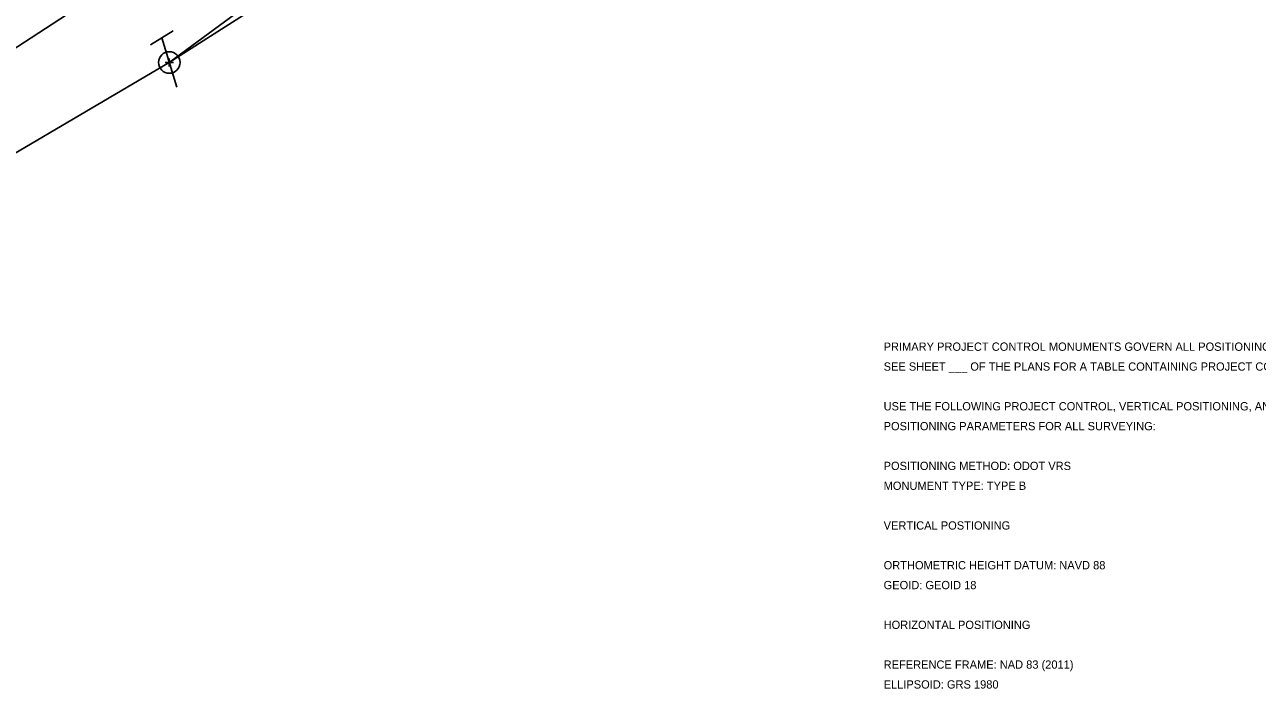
# Model space of a CAD drawing. Extents: x 2048206 to 2051708, y 354200 to 357644.
# Drawn here: x 2049380.8 to 2049529.9, y 356157.9 to 356238.7 of the extents above; entities that cross this region are included whole.
import ezdxf

# ---------------------------------------------------------------- set-up
doc = ezdxf.new("R2010")
doc.units = 0
for name, color, linetype in [('RW_X_CL_1000_Cardinal_Points', 7, 'Continuous'), ('RW_X_CL_500_Bearings', 7, 'Continuous'), ('SC_Scratch1', 7, 'Continuous'), ('SV_X_Text', 7, 'Continuous'), ('UT_X_Cable_TV', 7, 'Continuous')]:
    doc.layers.add(name, color=color, linetype=linetype)

msp = doc.modelspace()

# ---------------------------------------------------------------- linework, layer by layer
at = {"layer": 'RW_X_CL_1000_Cardinal_Points'}
for p in [(2049173.02, 356101.71), (2049173.02, 356101.71), (2049398.29, 356234.18), (2049398.29, 356234.18)]:
    msp.add_line(p, (2049557.32, 356351.32), dxfattribs=at)
at = {"layer": 'RW_X_CL_500_Bearings'}
for p, q in [((2049398.75, 356237.99), (2049396.03, 356236.31)), ((2049397.39, 356237.15), (2049399.18, 356231.2))]:
    msp.add_line(p, q, dxfattribs=at)
msp.add_circle((2049398.29, 356234.18), 1.3, dxfattribs=at)
at = {"layer": 'SC_Scratch1'}
for p, q in [((2049397.79, 356234.18), (2049398.79, 356234.18)), ((2049398.29, 356234.68), (2049398.29, 356233.68)), ((2049398.29, 356234.18), (2049398.29, 356234.18))]:
    msp.add_line(p, q, dxfattribs=at)
at = {"layer": 'UT_X_Cable_TV'}
msp.add_lwpolyline([(2049173.02, 356101.71), (2049398.29, 356234.18), (2049648.28, 356393.26), (2049839.38, 356550.87), (2049967.48, 356704.03)], dxfattribs=at)

# ---------------------------------------------------------------- texts
at = {"layer": 'SV_X_Text'}
for s, p in [('PRIMARY PROJECT CONTROL MONUMENTS GOVERN ALL POSITIONING ON ODOT PROJECTS.', (2049484.67, 356199.35)), ('SEE SHEET ___ OF THE PLANS FOR A TABLE CONTAINING PROJECT CONTROL INFORMATION.', (2049484.67, 356196.95)), ('USE THE FOLLOWING PROJECT CONTROL, VERTICAL POSITIONING, AND HORIZONTAL', (2049484.67, 356192.15)), ('POSITIONING PARAMETERS FOR ALL SURVEYING:', (2049484.67, 356189.75)), ('POSITIONING METHOD: ODOT VRS', (2049484.67, 356184.95)), ('MONUMENT TYPE: TYPE B', (2049484.67, 356182.55)), ('VERTICAL POSTIONING', (2049484.67, 356177.75)), ('ORTHOMETRIC HEIGHT DATUM: NAVD 88', (2049484.67, 356172.95)), ('GEOID: GEOID 18', (2049484.67, 356170.55)), ('HORIZONTAL POSITIONING', (2049484.67, 356165.75)), ('REFERENCE FRAME: NAD 83 (2011)', (2049484.67, 356160.95)), ('ELLIPSOID: GRS 1980', (2049484.67, 356158.55))]:
    msp.add_text(s, height=1, dxfattribs=at).set_placement(p)

doc.saveas('drawing.dxf')
